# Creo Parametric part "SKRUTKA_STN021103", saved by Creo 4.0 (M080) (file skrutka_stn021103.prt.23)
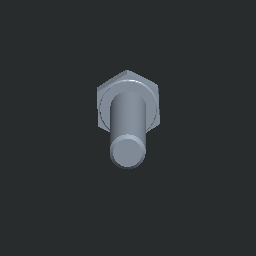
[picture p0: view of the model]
Units: Custom; MM, KILOGRAM, SECS
Materials in the file: OCEL_N

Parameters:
  WERKSTOFF = "8.8"
  KATEGORIE = "4"
  NAZOV = "SKRUTKA_STN021103"
  NORMA = "STN 02 1103"
  N1 = "021"
  N2 = "21"
  N3 = "1"
  NAZOV_1 = "START_PART_IPM"
  PTC_MATERIAL_NAME = "OCEL_N"
  PLACEMENT = "A"

Other parameters: HMOTNOST, HUSTOTA, HMOTNOST_1, THREADS_PER_INCH, D50, D2, D7, D25, D30

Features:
  1. chamfer
  2. datum plane "DTM1"
  3. protrusion
  4. datum plane "DTM6"
  5. cut
  6. datum plane "DTM7"
  7. cut
  8. datum plane "DTM8"
  9. datum plane "DTM9"

Layers: BEZUGSEBENEN, KONSTRUKTIONSELEMENTE, NORMTEILE

Family table entries: GENERIC, SKRUTKA_M3X4, SKRUTKA_STN021103, value(d_val), value(i_val), SKRUTKA_M3X5, SKRUTKA_STN021103, SKRUTKA_M3X6, SKRUTKA_STN021103, SKRUTKA_M3X8, SKRUTKA_STN021103, 2/ , SKRUTKA_M3X10, SKRUTKA_STN021103, 2/$, SKRUTKA_M3X12, SKRUTKA_STN021103, 2/(, SKRUTKA_M3X16, SKRUTKA_STN021103, 2/0, SKRUTKA_M3X20, SKRUTKA_STN021103, 2/4, SKRUTKA_M3X25, SKRUTKA_STN021103, 2/9, SKRUTKA_M3X30, SKRUTKA_STN021103, 2/>, SKRUTKA_M4X8, SKRUTKA_STN021103, 2/ , SKRUTKA_M4X10, SKRUTKA_STN021103, 2/$, SKRUTKA_M4X12, SKRUTKA_STN021103, 2/(, SKRUTKA_M4X16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

Surfaces: 10 plane, 4 cone, 3 cylinder, 2 torus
